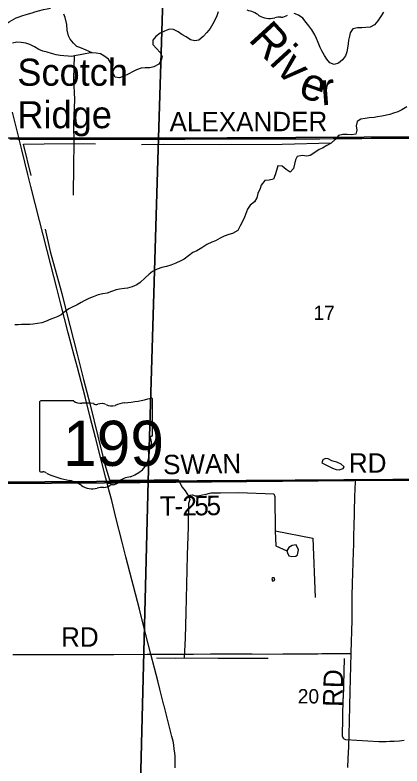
# Model space of a CAD drawing. Extents: x 1443599 to 1910620, y 1028088 to 1361369.
# Drawn here: x 1688334 to 1694297, y 1229998 to 1241579 of the extents above; entities that cross this region are included whole.
import ezdxf

# ---------------------------------------------------------------- set-up
doc = ezdxf.new("R2010")
doc.units = 0
for name, color, linetype in [('GM_X_Major_River', 7, 'Continuous'), ('GM_X_Major_River_Text', 7, 'Continuous'), ('GM_X_Minor_Lake', 7, 'Continuous'), ('GM_X_Minor_River', 7, 'Continuous'), ('GM_X_Section', 7, 'Continuous'), ('GM_X_Section_Text', 7, 'Continuous'), ('GM_X_State_Location', 7, 'Continuous'), ('GM_X_State_Route', 7, 'Continuous'), ('GM_X_State_Shield', 7, 'Continuous'), ('GM_X_Township', 7, 'Continuous'), ('GM_X_Township_Road', 7, 'Continuous'), ('GM_X_Township_Road_Text', 7, 'Continuous'), ('GM_X_Unincorporated_Text', 7, 'Continuous')]:
    doc.layers.add(name, color=color, linetype=linetype)

msp = doc.modelspace()

# ---------------------------------------------------------------- linework, layer by layer
at = {"layer": 'GM_X_Major_River'}
for points in [[(1691467, 1241626), (1691446, 1241568), (1691414, 1241499), (1691381, 1241441), (1691340, 1241372), (1691291, 1241308), (1691233, 1241245), (1691166, 1241192), (1691106, 1241183), (1691038, 1241197), (1690969, 1241242), (1690907, 1241280), (1690846, 1241319), (1690778, 1241354), (1690714, 1241360), (1690638, 1241329), (1690571, 1241298), (1690504, 1241249), (1690459, 1241190), (1690460, 1241126), (1690516, 1241060), (1690572, 1241003), (1690602, 1240938), (1690587, 1240884), (1690550, 1240823), (1690472, 1240778), (1690411, 1240765), (1690341, 1240763), (1690276, 1240758), (1690208, 1240731), (1690155, 1240706), (1690080, 1240669), (1690012, 1240636)], [(1694014, 1241624), (1693968, 1241552), (1693923, 1241491), (1693876, 1241428), (1693805, 1241393), (1693739, 1241388), (1693676, 1241383), (1693612, 1241380), (1693542, 1241366), (1693497, 1241306), (1693486, 1241252), (1693472, 1241190), (1693469, 1241136), (1693458, 1241070), (1693447, 1241010), (1693426, 1240951), (1693381, 1240887), (1693320, 1240836), (1693253, 1240817), (1693185, 1240843), (1693138, 1240900), (1693105, 1240957), (1693063, 1241026), (1693036, 1241080), (1693007, 1241153), (1692982, 1241216), (1692955, 1241271), (1692910, 1241350), (1692863, 1241413), (1692820, 1241464), (1692767, 1241529), (1692704, 1241574), (1692637, 1241604)], [(1690012, 1240636), (1689945, 1240610), (1689879, 1240621), (1689838, 1240696), (1689832, 1240768), (1689815, 1240831), (1689774, 1240898), (1689703, 1240947), (1689649, 1240979), (1689583, 1240992), (1689521, 1240995), (1689471, 1240988), (1689414, 1240980), (1689339, 1240966), (1689274, 1240952), (1689206, 1240941), (1689154, 1240942), (1689086, 1240949), (1689028, 1240956), (1688970, 1240967), (1688894, 1240987), (1688828, 1241004), (1688764, 1241021), (1688701, 1241049), (1688633, 1241086), (1688562, 1241126), (1688502, 1241147), (1688430, 1241156), (1688362, 1241162), (1688294, 1241143)]]:
    msp.add_lwpolyline(points, dxfattribs=at)
at = {"layer": 'GM_X_Minor_Lake'}
for p, q in [((1693295, 1234681), (1693253, 1234692)), ((1692553, 1233241), (1692602, 1233231)), ((1692295, 1232874), (1692299, 1232856))]:
    msp.add_line(p, q, dxfattribs=at)
for points in [[(1693253, 1234692), (1693216, 1234705), (1693159, 1234733), (1693121, 1234742), (1693078, 1234719), (1693063, 1234674), (1693102, 1234654), (1693229, 1234592), (1693284, 1234571), (1693330, 1234563), (1693393, 1234584), (1693404, 1234614), (1693359, 1234655), (1693295, 1234681)], [(1692602, 1233231), (1692659, 1233232), (1692688, 1233255), (1692704, 1233329), (1692668, 1233408), (1692606, 1233400), (1692551, 1233367), (1692525, 1233316), (1692532, 1233283), (1692553, 1233241)], [(1692299, 1232856), (1692315, 1232852), (1692340, 1232865), (1692329, 1232902), (1692307, 1232898), (1692294, 1232887), (1692295, 1232874)]]:
    msp.add_lwpolyline(points, dxfattribs=at)
at = {"layer": 'GM_X_Minor_River'}
for points in [[(1689521, 1240995), (1689428, 1241037), (1689335, 1241076), (1689287, 1241094), (1689236, 1241143), (1689184, 1241205), (1689157, 1241258), (1689140, 1241345), (1689134, 1241431), (1689105, 1241542), (1689085, 1241591)], [(1689245, 1240947), (1689237, 1240595), (1689250, 1240276), (1689235, 1239899), (1689240, 1239595), (1689233, 1239256), (1689232, 1238802)], [(1694371, 1240163), (1694294, 1240116), (1694233, 1240086), (1694169, 1240065), (1694110, 1240047), (1693988, 1240017)], [(1693988, 1240017), (1693918, 1240007), (1693866, 1240001), (1693793, 1239991), (1693729, 1239984), (1693665, 1239974), (1693605, 1239936), (1693593, 1239870), (1693602, 1239803), (1693588, 1239742), (1693519, 1239730), (1693455, 1239737), (1693385, 1239737), (1693319, 1239723), (1693267, 1239660), (1693207, 1239602), (1693138, 1239566), (1693073, 1239528), (1693022, 1239503), (1692954, 1239459), (1692883, 1239415), (1692831, 1239402), (1692757, 1239410), (1692684, 1239398), (1692655, 1239347), (1692639, 1239277), (1692625, 1239211), (1692575, 1239158), (1692512, 1239194), (1692451, 1239248), (1692383, 1239252), (1692361, 1239179), (1692343, 1239115), (1692315, 1239047), (1692249, 1239031), (1692184, 1239025), (1692126, 1238956), (1692111, 1238903), (1692075, 1238825), (1692061, 1238762), (1692027, 1238696), (1691957, 1238648), (1691919, 1238583), (1691868, 1238460), (1691840, 1238394), (1691802, 1238327), (1691766, 1238256), (1691688, 1238208), (1691628, 1238194), (1691559, 1238168), (1691494, 1238139), (1691423, 1238099), (1691366, 1238075), (1691289, 1238041), (1691215, 1237987), (1691136, 1237943), (1691075, 1237915), (1691009, 1237864), (1690942, 1237816), (1690887, 1237789), (1690813, 1237751), (1690736, 1237721), (1690666, 1237701), (1690599, 1237683), (1690526, 1237659), (1690451, 1237625), (1690400, 1237585), (1690338, 1237524), (1690262, 1237456), (1690211, 1237419), (1690140, 1237385), (1690069, 1237365), (1690019, 1237359), (1689946, 1237351), (1689892, 1237340), (1689819, 1237314), (1689754, 1237288), (1689686, 1237280), (1689613, 1237262), (1689540, 1237232), (1689471, 1237206), (1689402, 1237170), (1689351, 1237145), (1689290, 1237112), (1689217, 1237072), (1689164, 1237046), (1689113, 1237011), (1689045, 1236955), (1688994, 1236930), (1688942, 1236910), (1688885, 1236891), (1688802, 1236851), (1688749, 1236831), (1688682, 1236821), (1688614, 1236813), (1688560, 1236806), (1688510, 1236804), (1688434, 1236806), (1688381, 1236803), (1688331, 1236799)], [(1688583, 1239104), (1688465, 1239585), (1688783, 1239592), (1689240, 1239595), (1689575, 1239590)], [(1693207, 1239602), (1692453, 1239583), (1691507, 1239578), (1690615, 1239584), (1690284, 1239575)], [(1688798, 1238275), (1688878, 1237931), (1689054, 1237282), (1689128, 1236993), (1689177, 1236793), (1689294, 1236347), (1689389, 1235957), (1689491, 1235569), (1689611, 1235086), (1689717, 1234649), (1689792, 1234412), (1690103, 1234405), (1690476, 1234410), (1690849, 1234414), (1690877, 1234355), (1690909, 1234296), (1690958, 1234242), (1691010, 1234160), (1691026, 1234106), (1691007, 1234046), (1691002, 1233687), (1690988, 1233251), (1690975, 1232798), (1690965, 1232367), (1690958, 1231971), (1690939, 1231667)], [(1691010, 1234160), (1691034, 1234176), (1691071, 1234181), (1691110, 1234165), (1691154, 1234164), (1691221, 1234178), (1691279, 1234191), (1691356, 1234213), (1691502, 1234210), (1691781, 1234214), (1692322, 1234195), (1692339, 1234156), (1692345, 1233622), (1692353, 1233391), (1692525, 1233316)], [(1692345, 1233622), (1692924, 1233513), (1692960, 1232595)], [(1690514, 1231665), (1690802, 1231663), (1690939, 1231667), (1691464, 1231660), (1692235, 1231662)], [(1693404, 1231658), (1693392, 1231042)], [(1693942, 1230373), (1693433, 1230400), (1693401, 1230416), (1693378, 1230453), (1693392, 1231042)], [(1694331, 1230389), (1694261, 1230383), (1694178, 1230376), (1694112, 1230374), (1694052, 1230371), (1693998, 1230373), (1693942, 1230373)]]:
    msp.add_lwpolyline(points, dxfattribs=at)
at = {"layer": 'GM_X_Section'}
for points in [[(1685086, 1244953), (1690707, 1244955), (1690543, 1239680), (1684949, 1239688), (1684954, 1240120)], [(1695990, 1244984), (1695829, 1239703), (1690543, 1239680), (1690707, 1244955)], [(1684949, 1239688), (1690543, 1239680), (1690385, 1234393), (1684810, 1234353), (1684813, 1234803)], [(1695829, 1239703), (1695666, 1234426), (1690385, 1234393), (1690543, 1239680)], [(1684810, 1234353), (1690385, 1234393), (1690253, 1229120), (1684720, 1229091), (1684723, 1229473)], [(1690385, 1234393), (1695666, 1234426), (1695560, 1229121), (1690253, 1229120)]]:
    msp.add_lwpolyline(points, close=True, dxfattribs=at)
at = {"layer": 'GM_X_State_Route'}
for points in [[(1687666, 1241146), (1687669, 1241147), (1687711, 1241171), (1687728, 1241180), (1687814, 1241222), (1687864, 1241246), (1687958, 1241293), (1688007, 1241319), (1688049, 1241344), (1688104, 1241379), (1688180, 1241431), (1688243, 1241474), (1688279, 1241495), (1688314, 1241514), (1688353, 1241533), (1688399, 1241552), (1688439, 1241566), (1688505, 1241587), (1688599, 1241615), (1688640, 1241628), (1688697, 1241644), (1688771, 1241662), (1688828, 1241675), (1688882, 1241685)], [(1690631, 1230927), (1690628, 1230937), (1690566, 1231183), (1690534, 1231311), (1690483, 1231509), (1690429, 1231721), (1690388, 1231883), (1690309, 1232185), (1690250, 1232415), (1690043, 1233226), (1689987, 1233449), (1689890, 1233831), (1689824, 1234094), (1689791, 1234221), (1689756, 1234358), (1689736, 1234436), (1689667, 1234697), (1689575, 1235064), (1689489, 1235397), (1689413, 1235691), (1689296, 1236144), (1689247, 1236327), (1689155, 1236676), (1689041, 1237121), (1688976, 1237367), (1688886, 1237725), (1688712, 1238409), (1688580, 1238934), (1688534, 1239117), (1688438, 1239499), (1688397, 1239664), (1688391, 1239690), (1688336, 1239914), (1688294, 1240081)], [(1690801, 1229970), (1690803, 1230028), (1690803, 1230085), (1690801, 1230143), (1690796, 1230200), (1690789, 1230258), (1690779, 1230323), (1690769, 1230379), (1690752, 1230452), (1690700, 1230659), (1690631, 1230927)]]:
    msp.add_lwpolyline(points, dxfattribs=at)
at = {"layer": 'GM_X_State_Shield'}
for p, q in [((1689240, 1235627), (1688730, 1235627)), ((1690453, 1235100), (1690453, 1235653)), ((1688713, 1235609), (1688713, 1234552)), ((1690453, 1235100), (1690453, 1235100))]:
    msp.add_line(p, q, dxfattribs=at)
for centre, major_axis, start_param, end_param in [((1691810, 1241328), (417, 0), 0.823519, 1.323587), ((1692261, 1241737), (265, 0), 4.026481, 4.996735), ((1692414, 1241372), (217, 0), 1.495662, 1.94098), ((1692433, 1241658), (141, 0), 4.691044, 5.507374), ((1688733, 1235611), (20.2, 0), 1.712693, 3.28349), ((1689361, 1235749), (196, 0), 4.042523, 4.731795), ((1689834, 1237067), (1845, 0), 4.814394, 5.042369), ((1690434, 1235655), (19.4, 0), 6.141152, 7.989035), ((1689426, 1235033), (702, 0), 1.404758, 1.657858), ((1689586, 1235616), (56.4, 0), 3.836095, 5.185415), ((1689668, 1235494), (117, 0), 0.950623, 2.079405), ((1689820, 1235662), (141, 0), 4.081561, 5.145723), ((1690069, 1235304), (371, 0), 1.699011, 2.107814), ((1690449, 1235060), (30, 0), 1.883978, 3.671073), ((1690258, 1234990), (180, 0), 5.934695, 6.695948), ((1690433, 1235098), (20.7, 0), 5.05454, 6.418171), ((1690523, 1234869), (131, 0), 2.387724, 3.262537), ((1689937, 1234799), (462, 0), 5.101752, 6.440018), ((1688733, 1234550), (20.3, 0), 3.00124, 4.508301), ((1688736, 1234658), (155, 0), 4.665946, 4.897461), ((1688768, 1234491), (56, 0), 0.519207, 1.627899), ((1689475, 1235440), (1333, 0), 4.195997, 4.488961), ((1689077, 1234077), (417, 0), 0.823519, 1.323587), ((1689811, 1234449), (149, 0), 4.937069, 5.64225), ((1690132, 1234255), (253, 0), 1.647645, 2.488434), ((1689528, 1234486), (265, 0), 4.026481, 4.996735), ((1689681, 1234120), (217, 0), 1.495662, 1.94098), ((1689701, 1234407), (141, 0), 4.691044, 5.507374), ((1689828, 1234304), (39.7, 0), 1.147584, 2.315152)]:
    msp.add_ellipse(centre, major_axis=major_axis, ratio=0.8, start_param=start_param, end_param=end_param, dxfattribs=at)
at = {"layer": 'GM_X_Township'}
for points in [[(1695686, 1234412), (1693554, 1234401), (1689711, 1234366), (1684807, 1234336), (1684814, 1234779), (1682213, 1234819), (1679582, 1234813), (1676891, 1234863), (1674317, 1234889), (1674286, 1234890), (1674292, 1235244), (1674346, 1240281), (1674346, 1242746), (1674370, 1243215), (1674492, 1245523), (1674492, 1250747), (1671577, 1250816), (1669283, 1250871), (1669367, 1256110)], [(1695360, 1218494), (1693451, 1218508), (1690109, 1218505), (1689982, 1218509), (1687448, 1218622), (1684390, 1218758), (1684463, 1221594), (1684471, 1221885), (1684621, 1226450), (1684707, 1229066), (1684757, 1231793), (1684762, 1232099), (1684807, 1234336), (1689711, 1234366), (1693554, 1234401), (1695686, 1234412)]]:
    msp.add_lwpolyline(points, dxfattribs=at)
at = {"layer": 'GM_X_Township_Road'}
for points in [[(1688397, 1239664), (1688417, 1239663), (1688443, 1239662), (1688556, 1239662), (1688950, 1239663), (1689295, 1239664), (1689557, 1239663), (1690033, 1239664), (1690427, 1239664), (1690624, 1239665), (1690952, 1239666), (1691330, 1239668), (1691674, 1239668), (1691871, 1239669), (1692068, 1239669), (1692380, 1239670), (1692741, 1239671), (1692921, 1239671), (1693032, 1239672), (1693238, 1239673), (1693512, 1239674), (1693676, 1239675), (1693824, 1239678), (1693988, 1239679), (1694168, 1239680), (1694414, 1239679)], [(1688254, 1239665), (1688354, 1239667), (1688377, 1239666), (1688397, 1239664)], [(1689756, 1234358), (1689783, 1234360), (1689792, 1234360), (1689816, 1234362), (1689923, 1234363), (1690251, 1234370), (1690702, 1234378), (1690924, 1234381), (1691178, 1234384), (1691411, 1234387), (1691516, 1234389), (1691613, 1234392), (1691794, 1234396), (1691925, 1234397), (1691982, 1234397), (1692030, 1234397), (1692054, 1234398), (1692152, 1234399), (1692242, 1234400), (1692344, 1234400), (1692448, 1234400), (1692556, 1234400), (1692810, 1234403), (1692925, 1234404), (1693020, 1234405)], [(1693020, 1234405), (1693071, 1234406), (1693268, 1234406), (1693400, 1234405), (1693547, 1234406), (1693579, 1234407)], [(1693515, 1231734), (1693515, 1231745), (1693527, 1232245), (1693529, 1232319), (1693532, 1232508), (1693532, 1232590), (1693532, 1232647), (1693532, 1232688), (1693533, 1232746), (1693537, 1232836), (1693541, 1232951), (1693547, 1233156), (1693549, 1233279), (1693553, 1233435), (1693555, 1233533), (1693556, 1233582), (1693558, 1233664), (1693566, 1233927), (1693573, 1234148), (1693575, 1234271), (1693579, 1234377), (1693579, 1234407)], [(1693579, 1234407), (1693679, 1234407), (1694015, 1234406), (1694138, 1234405), (1694303, 1234404), (1694516, 1234404), (1694795, 1234403), (1695197, 1234403), (1695452, 1234402), (1695633, 1234402), (1695664, 1234402)], [(1688300, 1231716), (1688956, 1231717), (1689498, 1231719), (1689859, 1231720), (1690368, 1231721), (1690398, 1231722), (1690429, 1231721)], [(1690429, 1231721), (1690441, 1231721), (1690489, 1231721), (1690611, 1231722), (1690807, 1231724), (1691086, 1231725), (1691348, 1231729), (1691545, 1231729), (1691725, 1231728), (1691922, 1231726), (1691987, 1231726), (1692233, 1231725), (1692461, 1231726), (1692527, 1231727), (1692593, 1231728), (1692658, 1231729), (1692773, 1231729), (1692838, 1231729), (1692919, 1231729), (1692935, 1231729), (1692967, 1231730), (1692999, 1231730), (1693064, 1231731), (1693130, 1231732), (1693294, 1231733), (1693441, 1231733), (1693490, 1231734), (1693515, 1231734)], [(1693465, 1229973), (1693470, 1230113), (1693476, 1230293), (1693482, 1230482), (1693489, 1230687), (1693495, 1230925), (1693500, 1231146), (1693515, 1231734)]]:
    msp.add_lwpolyline(points, dxfattribs=at)

# ---------------------------------------------------------------- texts
at = {"layer": 'GM_X_Major_River_Text'}
for s, height, rotation, p in [('Riv', 500.3, 312.4276, (1691916, 1241194)), ('e', 500, 340.4288, (1692683, 1240334)), ('r', 500, 4.4307, (1693055, 1240184))]:
    msp.add_text(s, height=height, rotation=rotation, dxfattribs=at).set_placement(p)
at = {"layer": 'GM_X_Section_Text'}
for s, p in [('17', (1692933, 1236875)), ('20', (1692691, 1230963))]:
    msp.add_text(s, height=221, rotation=0, dxfattribs=at).set_placement(p)
at = {"layer": 'GM_X_State_Location'}
msp.add_text('199', height=1, rotation=0, dxfattribs=at).set_placement((1689211, 1234937))
for s in ['s', 'r']:
    msp.add_text(s, height=1, dxfattribs=at).set_placement((1689564, 1235010))
at = {"layer": 'GM_X_State_Shield'}
msp.add_text('199', height=696.1, dxfattribs=at).set_placement((1689076, 1234626))
at = {"layer": 'GM_X_Township_Road_Text'}
for s, rotation, p in [('ALEXANDER', 0.1125, (1690716, 1239783)), ('SWAN', 0.9228, (1690618, 1234495)), ('RD', 0, (1693479, 1234521)), ('T', 0.5957, (1690567, 1233856)), ('2', 0.6388, (1690915, 1233860)), ('5', 0.7651, (1691100, 1233862)), ('5', 1.291, (1691288, 1233864)), ('-', 0.5992, (1690791, 1233859)), ('RD', 0, (1689044, 1231837)), ('RD', 88.5306, (1693378, 1230907))]:
    msp.add_text(s, height=300, rotation=rotation, dxfattribs=at).set_placement(p)
at = {"layer": 'GM_X_Unincorporated_Text'}
for s, p in [('Scotch', (1688370, 1240488)), ('Ridge', (1688370, 1239833))]:
    msp.add_text(s, height=417, rotation=0, dxfattribs=at).set_placement(p)

doc.saveas('drawing.dxf')
